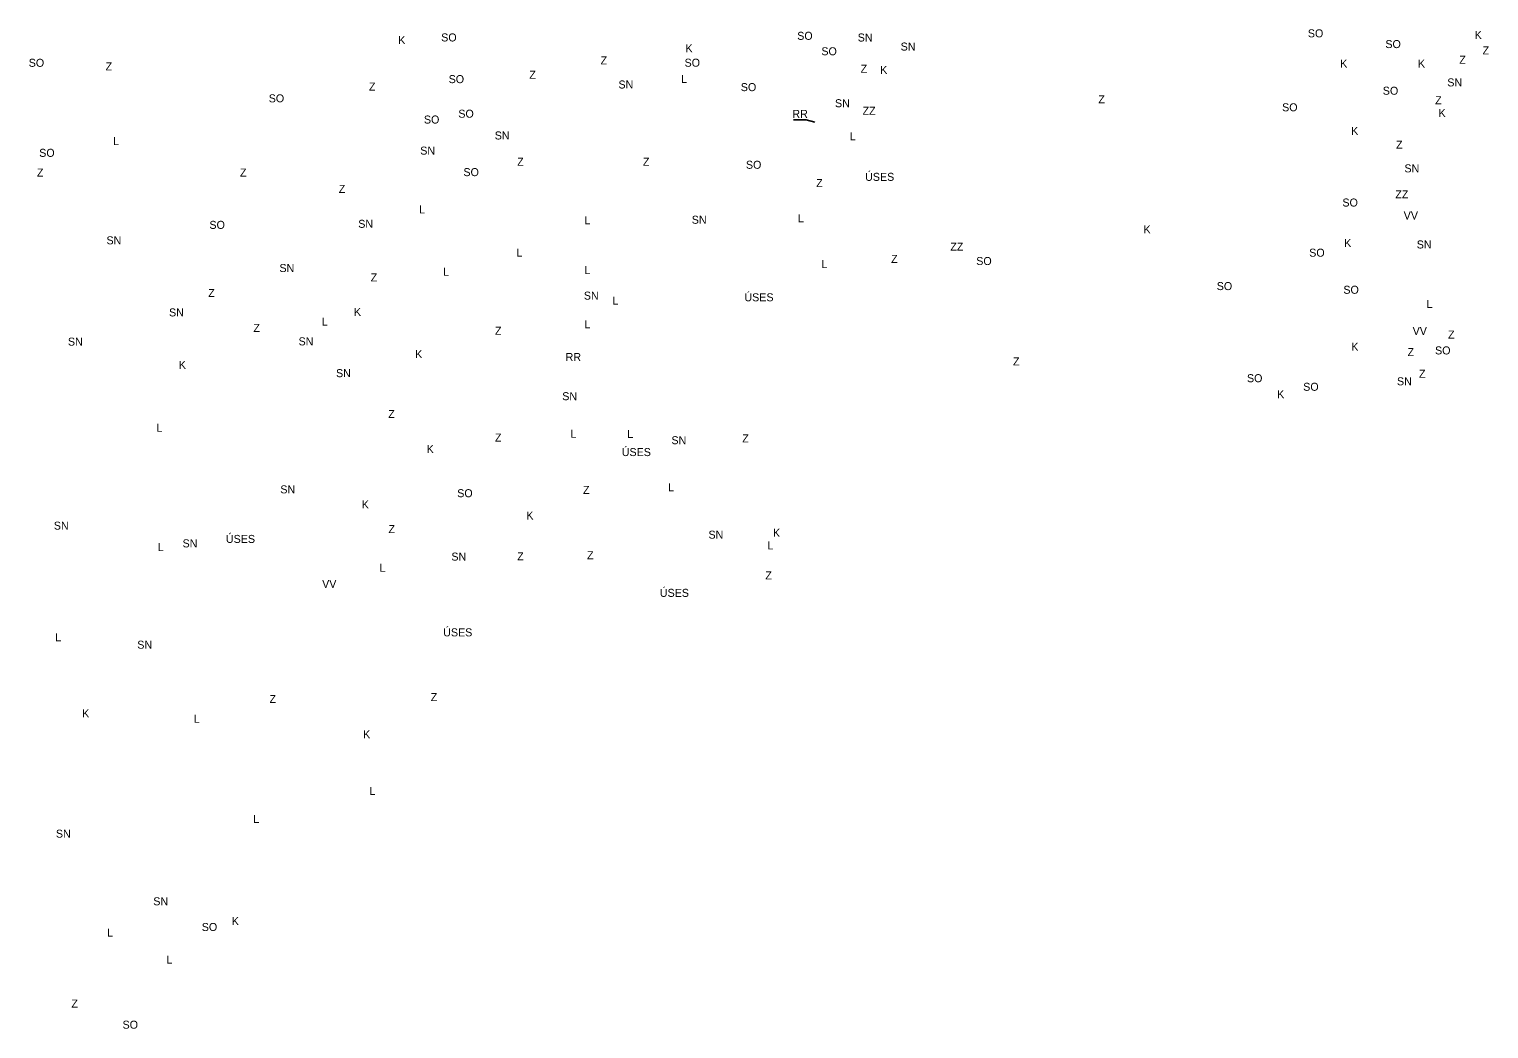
# Model space of a CAD drawing. Extents: x -445021 to -436233, y -1141846 to -1129798.
# Drawn here: x -443166 to -441341, y -1133410 to -1132161 of the extents above; entities that cross this region are included whole.
import ezdxf

# ---------------------------------------------------------------- set-up
doc = ezdxf.new("R2010")
doc.units = 0
doc.layers.add('Vrstva 4', color=7, linetype='Continuous')

msp = doc.modelspace()

# ---------------------------------------------------------------- linework, layer by layer
at = {"layer": 'Vrstva 4'}
msp.add_lwpolyline([(-442210.3, -1132274), (-442194.7, -1132274), (-442183.5, -1132276.8)], dxfattribs=at)

# ---------------------------------------------------------------- texts
for s, p in [('K', (-442704.4, -1132179.2)), ('SO', (-442650.7, -1132175.9)), ('SO', (-442205.7, -1132173.9)), ('SN', (-442130.1, -1132176)), ('SO', (-441567.4, -1132170.8)), ('K', (-441358.9, -1132172.9)), ('K', (-442345.3, -1132189.5)), ('SO', (-442175.5, -1132193.2)), ('SN', (-442076.4, -1132187.3)), ('SO', (-441470.5, -1132184.2)), ('Z', (-441349, -1132192.1)), ('SO', (-443166.3, -1132207.6)), ('Z', (-443070.2, -1132212.1)), ('Z', (-442451.5, -1132204.6)), ('SO', (-442346.5, -1132207.5)), ('Z', (-442126.4, -1132215)), ('K', (-442102, -1132216.5)), ('K', (-441527, -1132208.6)), ('K', (-441429.8, -1132208.6)), ('Z', (-441378.1, -1132203.8)), ('Z', (-442741, -1132237.3)), ('SO', (-442641.4, -1132228)), ('Z', (-442540.5, -1132222.5)), ('SN', (-442429.1, -1132234.7)), ('L', (-442350.7, -1132227.7)), ('SO', (-442276.2, -1132238)), ('SN', (-441393.1, -1132232.1)), ('SO', (-442866.3, -1132252)), ('Z', (-441829.3, -1132253.2)), ('SO', (-441473.7, -1132242.5)), ('Z', (-441408.3, -1132254.4)), ('SO', (-442629.3, -1132271.2)), ('RR', (-442211.8, -1132271.4)), ('SN', (-442158.5, -1132258.1)), ('ZZ', (-442124, -1132267.6)), ('SO', (-441599.6, -1132263.2)), ('K', (-441404, -1132270.3)), ('SO', (-442672.3, -1132278.5)), ('K', (-441513.3, -1132292.7)), ('L', (-443060.8, -1132305.5)), ('SN', (-442583.8, -1132298.4)), ('L', (-442140, -1132299.3)), ('Z', (-441457.1, -1132309.9)), ('SO', (-443153.2, -1132320.1)), ('SN', (-442676.9, -1132317.3)), ('Z', (-443156, -1132344.7)), ('Z', (-442902.2, -1132344.7)), ('SO', (-442622.9, -1132344.2)), ('Z', (-442555.7, -1132331.2)), ('Z', (-442398.5, -1132331.2)), ('SO', (-442269.8, -1132335)), ('ÚSES', (-442120.8, -1132350.1)), ('SN', (-441446.7, -1132339.5)), ('Z', (-442778.7, -1132365.1)), ('Z', (-442182, -1132357.9)), ('SO', (-441524.2, -1132382.2)), ('ZZ', (-441458.1, -1132372)), ('L', (-442678.4, -1132390.8)), ('L', (-442204.8, -1132401.9)), ('VV', (-441447.6, -1132398.4)), ('SO', (-442940.4, -1132410.1)), ('SN', (-442754.4, -1132408.8)), ('L', (-442471.7, -1132404.5)), ('SN', (-442337.5, -1132403.7)), ('K', (-441772.8, -1132415.8)), ('SN', (-443069.1, -1132429.4)), ('ZZ', (-442014.3, -1132437.3)), ('K', (-441522, -1132432.8)), ('SN', (-441431.3, -1132434.6)), ('L', (-442556.7, -1132444.7)), ('Z', (-442088.3, -1132452.6)), ('SO', (-441981.9, -1132455.3)), ('SO', (-441565.7, -1132444.9)), ('SN', (-442852.9, -1132464)), ('L', (-442648.4, -1132468.7)), ('L', (-442471.7, -1132466.6)), ('L', (-442175.5, -1132459.1)), ('Z', (-442738.8, -1132475.8)), ('SO', (-441681.3, -1132486.6)), ('SO', (-441523, -1132491.2)), ('Z', (-442941.9, -1132495.2)), ('SN', (-442472.4, -1132498.5)), ('L', (-442436.7, -1132504.8)), ('ÚSES', (-442271.7, -1132500.6)), ('L', (-441419, -1132508.8)), ('SN', (-442990.9, -1132519.5)), ('K', (-442759.8, -1132518.9)), ('Z', (-442885.4, -1132538.9)), ('L', (-442799.9, -1132531)), ('Z', (-442583.5, -1132542.5)), ('L', (-442471.7, -1132534.4)), ('VV', (-441436.4, -1132542.7)), ('Z', (-441392.1, -1132547.1)), ('SN', (-443117.3, -1132556)), ('SN', (-442829, -1132555.7)), ('K', (-441513.1, -1132562.4)), ('K', (-442683.2, -1132571.6)), ('RR', (-442495.2, -1132575.2)), ('Z', (-441935.9, -1132580.7)), ('Z', (-441442.8, -1132569.1)), ('SO', (-441408.4, -1132567)), ('K', (-442978.7, -1132585)), ('SN', (-442782.2, -1132595.4)), ('SO', (-441643.5, -1132601.7)), ('Z', (-441428.5, -1132596.2)), ('SO', (-441573.2, -1132612.4)), ('SN', (-441456, -1132605.6)), ('SN', (-442499.4, -1132624.2)), ('K', (-441605.8, -1132621.7)), ('Z', (-442716.9, -1132646.4)), ('L', (-443006.8, -1132663.7)), ('Z', (-442583.5, -1132675.9)), ('L', (-442489, -1132671.1)), ('L', (-442418.1, -1132671.4)), ('K', (-442668.9, -1132690.2)), ('ÚSES', (-442425, -1132694)), ('SN', (-442362.9, -1132679.2)), ('Z', (-442274.4, -1132676.9)), ('SN', (-442851.8, -1132740.6)), ('SO', (-442630.7, -1132745.4)), ('Z', (-442473.4, -1132741.2)), ('L', (-442367, -1132738.1)), ('K', (-442750, -1132759.5)), ('K', (-442544.3, -1132773.3)), ('SN', (-443134.9, -1132785.9)), ('ÚSES', (-442919.8, -1132802.5)), ('Z', (-442716.6, -1132790.2)), ('SN', (-442316.6, -1132797.2)), ('K', (-442236, -1132794.9)), ('L', (-443004.9, -1132812.7)), ('SN', (-442974, -1132808.1)), ('L', (-442243, -1132810.7)), ('L', (-442727.7, -1132838.6)), ('SN', (-442638, -1132824.6)), ('Z', (-442555.7, -1132824.3)), ('Z', (-442468.4, -1132822.9)), ('Z', (-442245.5, -1132848.1)), ('VV', (-442799.5, -1132858.7)), ('ÚSES', (-442377.4, -1132869.9)), ('L', (-443133.1, -1132925.4)), ('ÚSES', (-442648.2, -1132919.3)), ('SN', (-443030.6, -1132934.7)), ('Z', (-442865.3, -1133002.5)), ('Z', (-442663.8, -1133000.2)), ('K', (-443099.5, -1133020.5)), ('L', (-442960, -1133027.2)), ('K', (-442748.3, -1133046.6)), ('L', (-442740.5, -1133117.3)), ('L', (-442885.6, -1133152.4)), ('SN', (-443132.3, -1133170.8)), ('SN', (-443010.6, -1133255.3)), ('L', (-443068.4, -1133294.5)), ('SO', (-442950, -1133287.4)), ('K', (-442912.5, -1133280)), ('L', (-442994.1, -1133328.1)), ('Z', (-443113, -1133383.1)), ('SO', (-443049, -1133409.5))]:
    msp.add_text(s, height=10, dxfattribs=at).set_placement(p)

doc.saveas('drawing.dxf')
